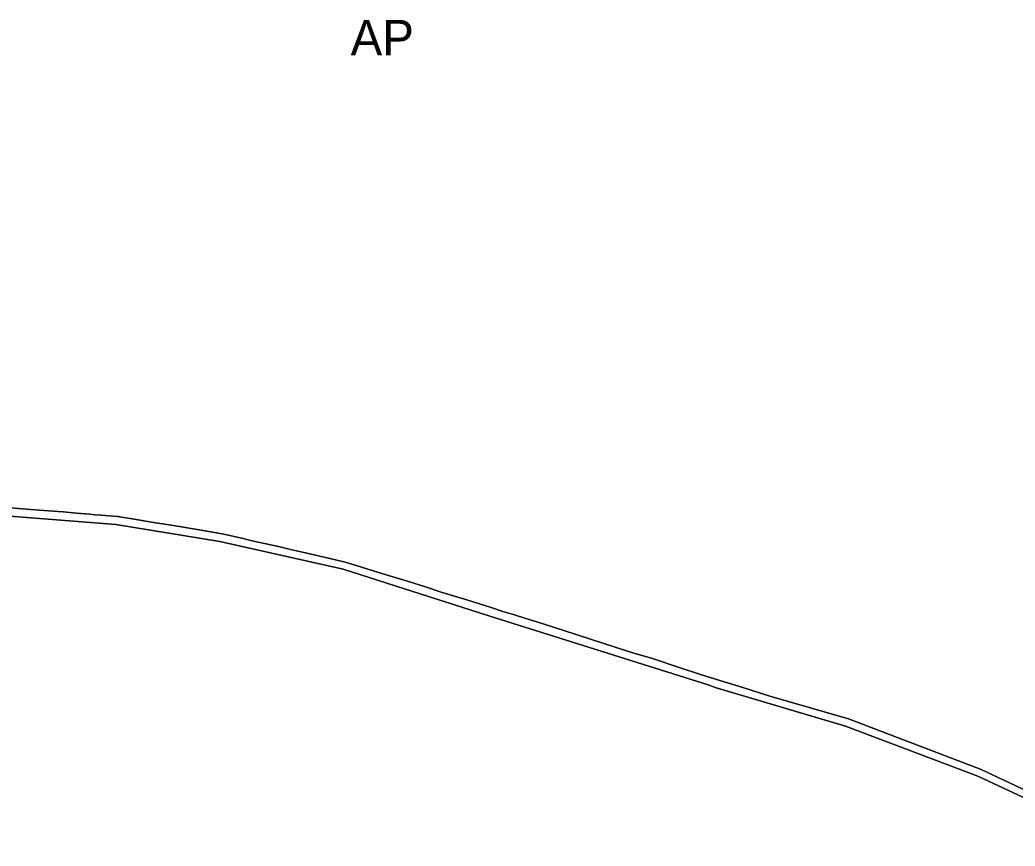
# Model space of a CAD drawing. Extents: x -555509 to -553005, y -1186756 to -1182560.
# Drawn here: x -554084.6 to -553691.8, y -1184039.1 to -1183712.7 of the extents above; entities that cross this region are included whole.
import ezdxf

# ---------------------------------------------------------------- set-up
doc = ezdxf.new("R2010")
doc.units = 0
for name, color, linetype in [('Level 26', 7, 'Continuous'), ('Level 59', 7, 'Continuous'), ('OBRYS_PLOCH', 7, 'Continuous'), ('stav_AP', 7, 'Continuous')]:
    doc.layers.add(name, color=color, linetype=linetype)

msp = doc.modelspace()

# ---------------------------------------------------------------- linework, layer by layer
at = {"layer": 'Level 26'}
for p, q in [((-554083.69, -1183905.82), (-554094.26, -1183904.9)), ((-554073.34, -1183906.59), (-554083.69, -1183905.82)), ((-554067.52, -1183907.03), (-554073.34, -1183906.59)), ((-554062.27, -1183907.57), (-554067.52, -1183907.03)), ((-554057.17, -1183908.02), (-554062.27, -1183907.57)), ((-554055.07, -1183908.18), (-554057.17, -1183908.02)), ((-554052.73, -1183908.33), (-554055.07, -1183908.18)), ((-554045.92, -1183908.89), (-554052.73, -1183908.33)), ((-554037.96, -1183910.26), (-554045.92, -1183908.89)), ((-554031.04, -1183911.34), (-554037.96, -1183910.26)), ((-554029.2, -1183911.63), (-554031.04, -1183911.34)), ((-554027.36, -1183911.92), (-554029.2, -1183911.63)), ((-554023.19, -1183912.63), (-554027.36, -1183911.92)), ((-554014.69, -1183913.98), (-554023.19, -1183912.63)), ((-554004.82, -1183915.7), (-554014.69, -1183913.98)), ((-553997.06, -1183917.42), (-554004.82, -1183915.7)), ((-553994.04, -1183918.19), (-553997.06, -1183917.42)), ((-553991.26, -1183918.83), (-553994.04, -1183918.19)), ((-553987.45, -1183919.72), (-553991.26, -1183918.83)), ((-553982.56, -1183920.75), (-553987.45, -1183919.72)), ((-553977.83, -1183921.85), (-553982.56, -1183920.75)), ((-553973.11, -1183922.96), (-553977.83, -1183921.85)), ((-553967.87, -1183924.2), (-553973.11, -1183922.96)), ((-553962.76, -1183925.31), (-553967.87, -1183924.2)), ((-553956.18, -1183926.97), (-553962.76, -1183925.31)), ((-553952.3, -1183928.14), (-553956.18, -1183926.97)), ((-553945.18, -1183930.29), (-553952.3, -1183928.14)), ((-553938.73, -1183932.36), (-553945.18, -1183930.29)), ((-553931.23, -1183934.58), (-553938.73, -1183932.36)), ((-553924.52, -1183936.72), (-553931.23, -1183934.58)), ((-553917.93, -1183938.84), (-553924.52, -1183936.72)), ((-553913.07, -1183940.33), (-553917.93, -1183938.84)), ((-553908.19, -1183941.86), (-553913.07, -1183940.33)), ((-553903.24, -1183943.33), (-553908.19, -1183941.86)), ((-553898.56, -1183944.87), (-553903.24, -1183943.33)), ((-553893.93, -1183946.36), (-553898.56, -1183944.87)), ((-553889.37, -1183947.78), (-553893.93, -1183946.36)), ((-553884.96, -1183949.22), (-553889.37, -1183947.78)), ((-553880.62, -1183950.54), (-553884.96, -1183949.22)), ((-553874.81, -1183952.34), (-553880.62, -1183950.54)), ((-553849.2, -1183960.58), (-553874.81, -1183952.34)), ((-553842.6, -1183962.69), (-553849.2, -1183960.58)), ((-553834.91, -1183965.01), (-553842.6, -1183962.69)), ((-553824.44, -1183968.51), (-553834.91, -1183965.01)), ((-553816.37, -1183971.17), (-553824.44, -1183968.51)), ((-553808.28, -1183973.73), (-553816.37, -1183971.17)), ((-553799.3, -1183976.47), (-553808.28, -1183973.73)), ((-553788.59, -1183979.88), (-553799.3, -1183976.47)), ((-553757.54, -1183988.79), (-553788.59, -1183979.88)), ((-553705.13, -1184008.79), (-553757.54, -1183988.79)), ((-553668.01, -1184026.33), (-553705.13, -1184008.79))]:
    msp.add_line(p, q, dxfattribs=at)
for points in [[(-554118.07, -1183915.18), (-554110.39, -1183907.02), (-554046.81, -1183912.08), (-554005.63, -1183918.73), (-553956.98, -1183929.73), (-553899.51, -1183948.08), (-553812.95, -1183975.4)], [(-553812.95, -1183975.4), (-553810.12, -1183976.41), (-553758.78, -1183991.72), (-553706.5, -1184011.48), (-553669.19, -1184028.85), (-553614.46, -1184064.51), (-553594.78, -1184077.06)]]:
    msp.add_lwpolyline(points, dxfattribs=at)
at = {"layer": 'OBRYS_PLOCH'}
for p, q in [((-554083.69, -1183905.82), (-554094.26, -1183904.9)), ((-554094.26, -1183904.9), (-554083.69, -1183905.82)), ((-554073.34, -1183906.59), (-554083.69, -1183905.82)), ((-554083.69, -1183905.82), (-554073.34, -1183906.59)), ((-554067.52, -1183907.03), (-554073.34, -1183906.59)), ((-554073.34, -1183906.59), (-554067.52, -1183907.03)), ((-554062.27, -1183907.57), (-554067.52, -1183907.03)), ((-554067.52, -1183907.03), (-554062.27, -1183907.57)), ((-554057.17, -1183908.02), (-554062.27, -1183907.57)), ((-554062.27, -1183907.57), (-554057.17, -1183908.02)), ((-554055.07, -1183908.18), (-554057.17, -1183908.02)), ((-554057.17, -1183908.02), (-554055.07, -1183908.18)), ((-554052.73, -1183908.33), (-554055.07, -1183908.18)), ((-554055.07, -1183908.18), (-554052.73, -1183908.33)), ((-554045.92, -1183908.89), (-554052.73, -1183908.33)), ((-554052.73, -1183908.33), (-554045.92, -1183908.89)), ((-554037.96, -1183910.26), (-554045.92, -1183908.89)), ((-554045.92, -1183908.89), (-554037.96, -1183910.26)), ((-554031.04, -1183911.34), (-554037.96, -1183910.26)), ((-554037.96, -1183910.26), (-554031.04, -1183911.34)), ((-554029.2, -1183911.63), (-554031.04, -1183911.34)), ((-554031.04, -1183911.34), (-554029.2, -1183911.63)), ((-554027.36, -1183911.92), (-554029.2, -1183911.63)), ((-554029.2, -1183911.63), (-554027.36, -1183911.92)), ((-554023.19, -1183912.63), (-554027.36, -1183911.92)), ((-554027.36, -1183911.92), (-554023.19, -1183912.63)), ((-554014.69, -1183913.98), (-554023.19, -1183912.63)), ((-554023.19, -1183912.63), (-554014.69, -1183913.98)), ((-554004.82, -1183915.7), (-554014.69, -1183913.98)), ((-554014.69, -1183913.98), (-554004.82, -1183915.7)), ((-553997.06, -1183917.42), (-554004.82, -1183915.7)), ((-554004.82, -1183915.7), (-553997.06, -1183917.42)), ((-553994.04, -1183918.19), (-553997.06, -1183917.42)), ((-553997.06, -1183917.42), (-553994.04, -1183918.19)), ((-553991.26, -1183918.83), (-553994.04, -1183918.19)), ((-553994.04, -1183918.19), (-553991.26, -1183918.83)), ((-553987.45, -1183919.72), (-553991.26, -1183918.83)), ((-553991.26, -1183918.83), (-553987.45, -1183919.72)), ((-553982.56, -1183920.75), (-553987.45, -1183919.72)), ((-553987.45, -1183919.72), (-553982.56, -1183920.75)), ((-553977.83, -1183921.85), (-553982.56, -1183920.75)), ((-553982.56, -1183920.75), (-553977.83, -1183921.85)), ((-553973.11, -1183922.96), (-553977.83, -1183921.85)), ((-553977.83, -1183921.85), (-553973.11, -1183922.96)), ((-553967.87, -1183924.2), (-553973.11, -1183922.96)), ((-553973.11, -1183922.96), (-553967.87, -1183924.2)), ((-553962.76, -1183925.31), (-553967.87, -1183924.2)), ((-553967.87, -1183924.2), (-553962.76, -1183925.31)), ((-553956.18, -1183926.97), (-553962.76, -1183925.31)), ((-553962.76, -1183925.31), (-553956.18, -1183926.97)), ((-553952.3, -1183928.14), (-553956.18, -1183926.97)), ((-553956.18, -1183926.97), (-553952.3, -1183928.14)), ((-553945.18, -1183930.29), (-553952.3, -1183928.14)), ((-553952.3, -1183928.14), (-553945.18, -1183930.29)), ((-553938.73, -1183932.36), (-553945.18, -1183930.29)), ((-553945.18, -1183930.29), (-553938.73, -1183932.36)), ((-553931.23, -1183934.58), (-553938.73, -1183932.36)), ((-553938.73, -1183932.36), (-553931.23, -1183934.58)), ((-553924.52, -1183936.72), (-553931.23, -1183934.58)), ((-553931.23, -1183934.58), (-553924.52, -1183936.72)), ((-553917.93, -1183938.84), (-553924.52, -1183936.72)), ((-553924.52, -1183936.72), (-553917.93, -1183938.84)), ((-553913.07, -1183940.33), (-553917.93, -1183938.84)), ((-553917.93, -1183938.84), (-553913.07, -1183940.33)), ((-553908.19, -1183941.86), (-553913.07, -1183940.33)), ((-553913.07, -1183940.33), (-553908.19, -1183941.86)), ((-553903.24, -1183943.33), (-553908.19, -1183941.86)), ((-553908.19, -1183941.86), (-553903.24, -1183943.33)), ((-553898.56, -1183944.87), (-553903.24, -1183943.33)), ((-553903.24, -1183943.33), (-553898.56, -1183944.87)), ((-553893.93, -1183946.36), (-553898.56, -1183944.87)), ((-553898.56, -1183944.87), (-553893.93, -1183946.36)), ((-553889.37, -1183947.78), (-553893.93, -1183946.36)), ((-553893.93, -1183946.36), (-553889.37, -1183947.78)), ((-553884.96, -1183949.22), (-553889.37, -1183947.78)), ((-553889.37, -1183947.78), (-553884.96, -1183949.22)), ((-553880.62, -1183950.54), (-553884.96, -1183949.22)), ((-553884.96, -1183949.22), (-553880.62, -1183950.54)), ((-553874.81, -1183952.34), (-553880.62, -1183950.54)), ((-553880.62, -1183950.54), (-553874.81, -1183952.34)), ((-553849.2, -1183960.58), (-553874.81, -1183952.34)), ((-553874.81, -1183952.34), (-553849.2, -1183960.58)), ((-553842.6, -1183962.69), (-553849.2, -1183960.58)), ((-553849.2, -1183960.58), (-553842.6, -1183962.69)), ((-553834.91, -1183965.01), (-553842.6, -1183962.69)), ((-553842.6, -1183962.69), (-553834.91, -1183965.01)), ((-553824.44, -1183968.51), (-553834.91, -1183965.01)), ((-553834.91, -1183965.01), (-553824.44, -1183968.51)), ((-553816.37, -1183971.17), (-553824.44, -1183968.51)), ((-553824.44, -1183968.51), (-553816.37, -1183971.17)), ((-553808.28, -1183973.73), (-553816.37, -1183971.17)), ((-553816.37, -1183971.17), (-553808.28, -1183973.73)), ((-553799.3, -1183976.47), (-553808.28, -1183973.73)), ((-553808.28, -1183973.73), (-553799.3, -1183976.47)), ((-553788.59, -1183979.88), (-553799.3, -1183976.47)), ((-553799.3, -1183976.47), (-553788.59, -1183979.88)), ((-553757.54, -1183988.79), (-553788.59, -1183979.88)), ((-553788.59, -1183979.88), (-553757.54, -1183988.79)), ((-553705.13, -1184008.79), (-553757.54, -1183988.79)), ((-553757.54, -1183988.79), (-553705.13, -1184008.79)), ((-553668.01, -1184026.33), (-553705.13, -1184008.79)), ((-553705.13, -1184008.79), (-553668.01, -1184026.33))]:
    msp.add_line(p, q, dxfattribs=at)
for points in [[(-554118.07, -1183915.18), (-554110.39, -1183907.02), (-554046.81, -1183912.08), (-554005.63, -1183918.73), (-553956.98, -1183929.73), (-553899.51, -1183948.08), (-553812.95, -1183975.4)], [(-553812.95, -1183975.4), (-553899.51, -1183948.08), (-553956.98, -1183929.73), (-554005.63, -1183918.73), (-554046.81, -1183912.08), (-554110.39, -1183907.02), (-554118.07, -1183915.18)], [(-553812.95, -1183975.4), (-553810.12, -1183976.41), (-553758.78, -1183991.72), (-553706.5, -1184011.48), (-553669.19, -1184028.85), (-553614.46, -1184064.51), (-553594.78, -1184077.06)], [(-553594.78, -1184077.06), (-553614.46, -1184064.51), (-553669.19, -1184028.85), (-553706.5, -1184011.48), (-553758.78, -1183991.72), (-553810.12, -1183976.41), (-553812.95, -1183975.4)]]:
    msp.add_lwpolyline(points, dxfattribs=at)
at = {"layer": 'stav_AP'}
for p, q in [((-554094.26, -1183904.9), (-554083.69, -1183905.82)), ((-554083.69, -1183905.82), (-554073.34, -1183906.59)), ((-554073.34, -1183906.59), (-554067.52, -1183907.03)), ((-554067.52, -1183907.03), (-554062.27, -1183907.57)), ((-554062.27, -1183907.57), (-554057.17, -1183908.02)), ((-554057.17, -1183908.02), (-554055.07, -1183908.18)), ((-554055.07, -1183908.18), (-554052.73, -1183908.33)), ((-554052.73, -1183908.33), (-554045.92, -1183908.89)), ((-554045.92, -1183908.89), (-554037.96, -1183910.26)), ((-554037.96, -1183910.26), (-554031.04, -1183911.34)), ((-554031.04, -1183911.34), (-554029.2, -1183911.63)), ((-554029.2, -1183911.63), (-554027.36, -1183911.92)), ((-554027.36, -1183911.92), (-554023.19, -1183912.63)), ((-554023.19, -1183912.63), (-554014.69, -1183913.98)), ((-554014.69, -1183913.98), (-554004.82, -1183915.7)), ((-554004.82, -1183915.7), (-553997.06, -1183917.42)), ((-553997.06, -1183917.42), (-553994.04, -1183918.19)), ((-553994.04, -1183918.19), (-553991.26, -1183918.83)), ((-553991.26, -1183918.83), (-553987.45, -1183919.72)), ((-553987.45, -1183919.72), (-553982.56, -1183920.75)), ((-553982.56, -1183920.75), (-553977.83, -1183921.85)), ((-553977.83, -1183921.85), (-553973.11, -1183922.96)), ((-553973.11, -1183922.96), (-553967.87, -1183924.2)), ((-553967.87, -1183924.2), (-553962.76, -1183925.31)), ((-553962.76, -1183925.31), (-553956.18, -1183926.97)), ((-553956.18, -1183926.97), (-553952.3, -1183928.14)), ((-553952.3, -1183928.14), (-553945.18, -1183930.29)), ((-553945.18, -1183930.29), (-553938.73, -1183932.36)), ((-553938.73, -1183932.36), (-553931.23, -1183934.58)), ((-553931.23, -1183934.58), (-553924.52, -1183936.72)), ((-553924.52, -1183936.72), (-553917.93, -1183938.84)), ((-553917.93, -1183938.84), (-553913.07, -1183940.33)), ((-553913.07, -1183940.33), (-553908.19, -1183941.86)), ((-553908.19, -1183941.86), (-553903.24, -1183943.33)), ((-553903.24, -1183943.33), (-553898.56, -1183944.87)), ((-553898.56, -1183944.87), (-553893.93, -1183946.36)), ((-553893.93, -1183946.36), (-553889.37, -1183947.78)), ((-553889.37, -1183947.78), (-553884.96, -1183949.22)), ((-553884.96, -1183949.22), (-553880.62, -1183950.54)), ((-553880.62, -1183950.54), (-553874.81, -1183952.34)), ((-553874.81, -1183952.34), (-553849.2, -1183960.58)), ((-553849.2, -1183960.58), (-553842.6, -1183962.69)), ((-553842.6, -1183962.69), (-553834.91, -1183965.01)), ((-553834.91, -1183965.01), (-553824.44, -1183968.51)), ((-553824.44, -1183968.51), (-553816.37, -1183971.17)), ((-553816.37, -1183971.17), (-553808.28, -1183973.73)), ((-553808.28, -1183973.73), (-553799.3, -1183976.47)), ((-553799.3, -1183976.47), (-553788.59, -1183979.88)), ((-553788.59, -1183979.88), (-553757.54, -1183988.79)), ((-553757.54, -1183988.79), (-553705.13, -1184008.79)), ((-553705.13, -1184008.79), (-553668.01, -1184026.33))]:
    msp.add_line(p, q, dxfattribs=at)
for points in [[(-553812.95, -1183975.4), (-553899.51, -1183948.08), (-553956.98, -1183929.73), (-554005.63, -1183918.73), (-554046.81, -1183912.08), (-554110.39, -1183907.02), (-554118.07, -1183915.18)], [(-553594.78, -1184077.06), (-553614.46, -1184064.51), (-553669.19, -1184028.85), (-553706.5, -1184011.48), (-553758.78, -1183991.72), (-553810.12, -1183976.41), (-553812.95, -1183975.4)]]:
    msp.add_lwpolyline(points, dxfattribs=at)

# ---------------------------------------------------------------- texts
at = {"layer": 'Level 59'}
msp.add_text('AP', height=14, dxfattribs=at).set_placement((-553954.07, -1183726.69))

doc.saveas('drawing.dxf')
